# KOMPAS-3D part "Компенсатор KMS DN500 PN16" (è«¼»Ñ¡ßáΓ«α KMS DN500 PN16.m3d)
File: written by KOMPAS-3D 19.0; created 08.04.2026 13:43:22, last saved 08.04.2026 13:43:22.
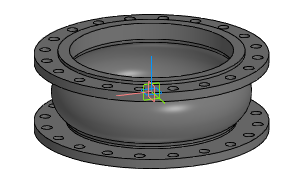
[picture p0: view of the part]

Document properties: Автор: Энергия; Полное имя файла: Z:\3.Личные\kachalov\3d для проектировщиков\7.1 Компенсатор\stp_Компенсатор KSM\Компенсатор KMS DN500 PN16.m3d

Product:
- Part/product: Компенсатор KMS DN500 PN16

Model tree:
1. Операция без истории:1  (labels: Компенсатор KMS DN500 PN16)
